(* Logix 5000 project; controller ANG1E_AOI_sample_RSLogix_V31 vendor 1 type 14 code 108 rev 31.11; software revision 31.02; part 5 of 5 *)

ADD_ON_INSTRUCTION AMCI_ANG1E_Reset_Errors   (* revision 1.1, vendor AMCI *)
// Revision note:
// Version 1.1 added the slot_axis number and the input parameters can now be tags or discrete values.
VAR_INPUT
   slot_axis_number : INT; {required}
END_VAR
VAR_IN_OUT
   AMCI_ANG1E_output_data : INT[10]; {required}
END_VAR
VAR
   command_data_block : INT[10];
        [1]   // Command Bits LSW
        [3]   // Lower Target Position
        [5]   // Lower Programmed Speed
        [0]   // Command Bits MSW
        [2]   // Upper Target Position
        [4]   // Upper Programmed Speed
   index : INT;
END_VAR

ROUTINE Logic   (* ladder *)
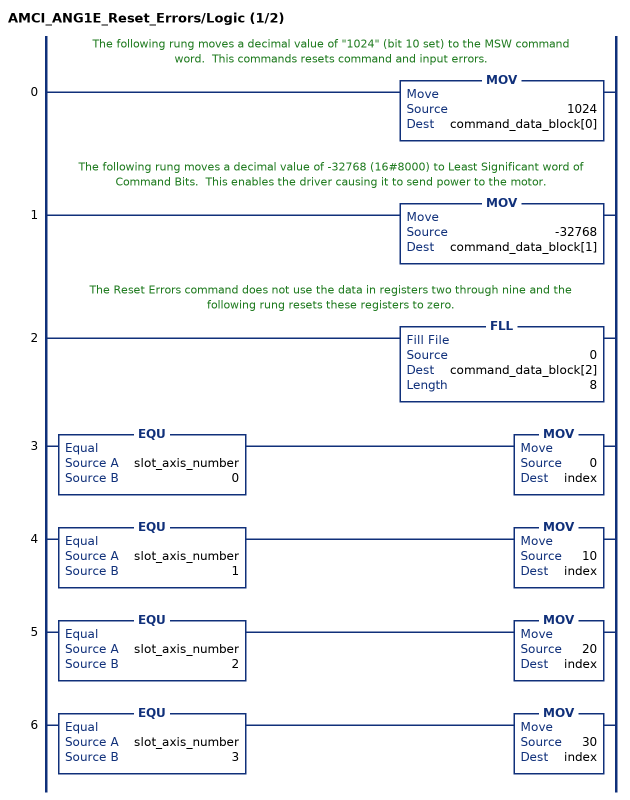
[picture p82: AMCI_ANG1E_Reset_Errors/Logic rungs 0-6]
   // The following rung moves a decimal value of "1024" (bit 10 set) to the MSW command word.  This commands resets command and input errors.
   0: MOV(1024,command_data_block[0]);
   // The following rung moves a decimal value of -32768 (16#8000) to Least Significant word of Command Bits.  This enables the driver causing it to send power to the motor.
   1: MOV(-32768,command_data_block[1]);
   // The Reset Errors command does not use the data in registers two through nine and the following rung resets these registers to zero.
   2: FLL(0,command_data_block[2],8);
   3: EQU(slot_axis_number,0)MOV(0,index);
   4: EQU(slot_axis_number,1)MOV(10,index);
   5: EQU(slot_axis_number,2)MOV(20,index);
   6: EQU(slot_axis_number,3)MOV(30,index);
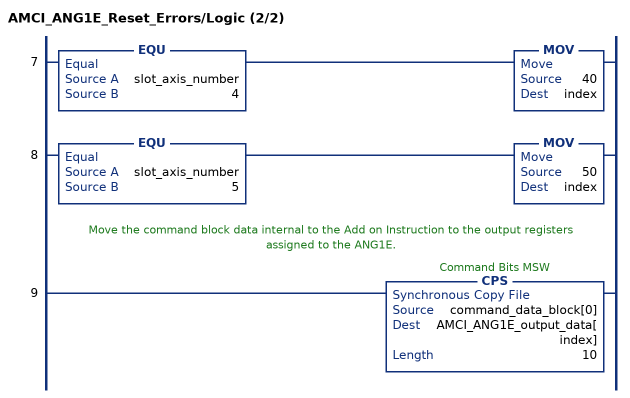
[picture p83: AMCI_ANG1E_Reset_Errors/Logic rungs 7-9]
   7: EQU(slot_axis_number,4)MOV(40,index);
   8: EQU(slot_axis_number,5)MOV(50,index);
   // Move the command block data internal to the Add on Instruction to the output registers assigned to the ANG1E.
   9: CPS(command_data_block[0],AMCI_ANG1E_output_data[index],10);
END_ROUTINE
END_ADD_ON_INSTRUCTION

ADD_ON_INSTRUCTION AMCI_ANG1E_Resume   (* revision 2.0, vendor AMCI *)
// Revision note:
// Version 1.1 added the slot_axis number and the input parameters can now be tags or discrete values.
// 12/4/2023, revision 2.0: Modified AOI so it only writes to output words 0 and 1.
VAR_INPUT
   slot_axis_number : INT; {required}
END_VAR
VAR_IN_OUT
   AMCI_ANG1E_output_data : INT[10]; {required}
END_VAR
VAR
   command_data_block : INT[10];
        [1]   // Command Bits LSW
        [3]   // Lower Target Position
        [5]   // Lower Programmed Speed
        [0]   // Command Bits MSW
        [2]   // Upper Target Position
        [4]   // Upper Programmed Speed
   index : INT;
END_VAR

ROUTINE Logic   (* ladder *)
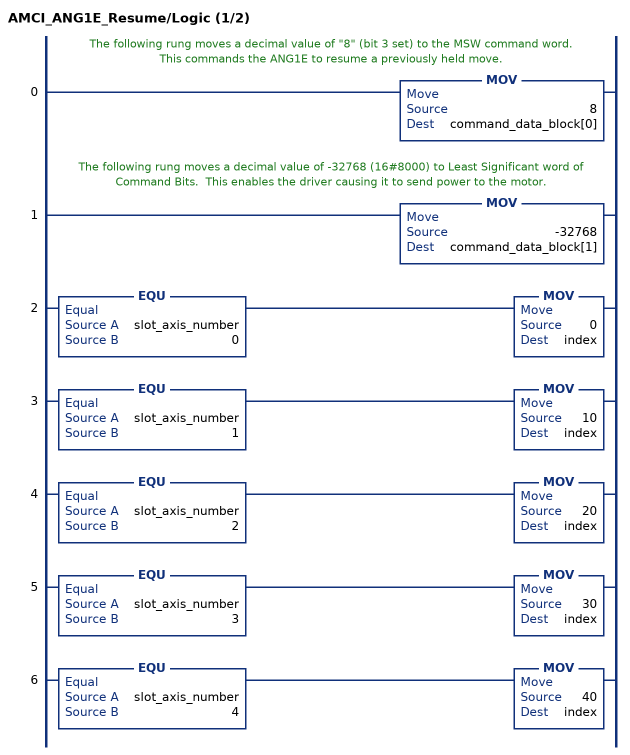
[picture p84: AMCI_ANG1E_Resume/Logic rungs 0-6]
   // The following rung moves a decimal value of "8" (bit 3 set) to the MSW command word.  This commands the ANG1E to resume a previously held move.
   0: MOV(8,command_data_block[0]);
   // The following rung moves a decimal value of -32768 (16#8000) to Least Significant word of Command Bits.  This enables the driver causing it to send power to the motor.
   1: MOV(-32768,command_data_block[1]);
   2: EQU(slot_axis_number,0)MOV(0,index);
   3: EQU(slot_axis_number,1)MOV(10,index);
   4: EQU(slot_axis_number,2)MOV(20,index);
   5: EQU(slot_axis_number,3)MOV(30,index);
   6: EQU(slot_axis_number,4)MOV(40,index);
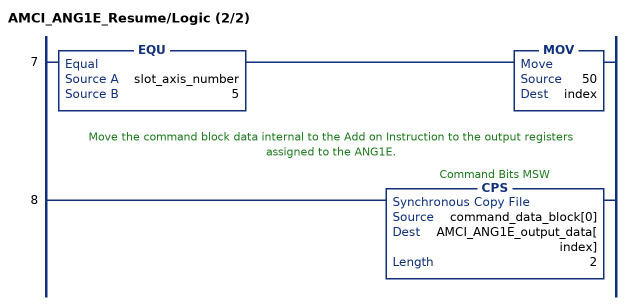
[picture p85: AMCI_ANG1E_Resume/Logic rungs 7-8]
   7: EQU(slot_axis_number,5)MOV(50,index);
   // Move the command block data internal to the Add on Instruction to the output registers assigned to the ANG1E.
   8: CPS(command_data_block[0],AMCI_ANG1E_output_data[index],2);
END_ROUTINE
END_ADD_ON_INSTRUCTION

ADD_ON_INSTRUCTION AMCI_ANG1E_Run_Blend_Move   (* revision 5.0, vendor AMCI, ExecuteEnableInFalse *)
// Revision note:
// Version 5.0 added the (hidden) ability to program the motor current and unlatched the error bit if the rung goes false.
VAR_INPUT
   Axis_Status_bits : INT; {required}
   slot_axis_number : INT; {required}
   Direction_0_for_CW_1_for_CCW : BOOL; {required}
   Type_0_for_standard_1_for_indexed : BOOL;
   motor_current : INT;
END_VAR
VAR_IN_OUT
   AMCI_ANG1E_output_data : INT[10]; {required}
END_VAR
VAR_OUTPUT
   EN : BOOL; {access Read Only, visible}
   ER : BOOL; {access Read Only, visible}
END_VAR
VAR
   command_data_block : INT[10];
        [1]   // Command Bits LSW
        [3]   // Lower Target Position
        [5]   // Lower Programmed Speed
        [0]   // Command Bits MSW
        [2]   // Upper Target Position
        [4]   // Upper Programmed Speed
   index : INT;
END_VAR

ROUTINE EnableInFalse   (* ladder *)
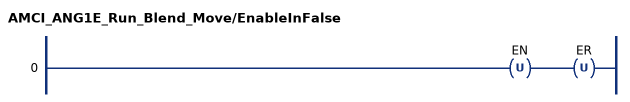
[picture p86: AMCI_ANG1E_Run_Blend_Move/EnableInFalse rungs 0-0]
   0: OTU(EN)OTU(ER);
END_ROUTINE

ROUTINE Logic   (* ladder *)
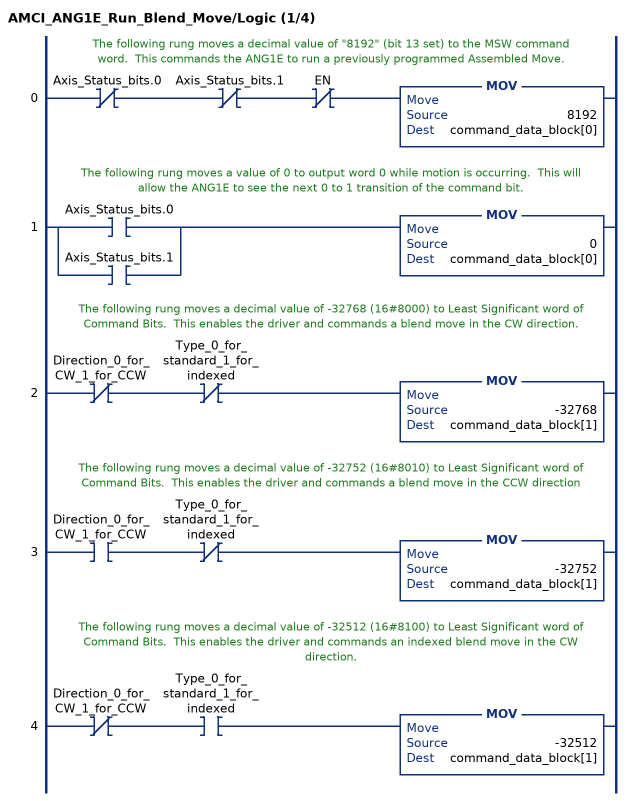
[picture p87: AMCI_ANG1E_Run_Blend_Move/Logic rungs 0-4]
   // The following rung moves a decimal value of "8192" (bit 13 set) to the MSW command word.  This commands the ANG1E to run a previously programmed Assembled Move.
   0: XIO(Axis_Status_bits.0)XIO(Axis_Status_bits.1)XIO(EN)MOV(8192,command_data_block[0]);
   // The following rung moves a value of 0 to output word 0 while motion is occurring.  This will allow the ANG1E to see the next 0 to 1 transition of the command bit.
   1: [XIC(Axis_Status_bits.0) ,XIC(Axis_Status_bits.1) ]MOV(0,command_data_block[0]);
   // The following rung moves a decimal value of -32768 (16#8000) to Least Significant word of Command Bits.  This enables the driver and commands a blend move in the CW direction.
   2: XIO(Direction_0_for_CW_1_for_CCW)XIO(Type_0_for_standard_1_for_indexed)MOV(-32768,command_data_block[1]);
   // The following rung moves a decimal value of -32752 (16#8010) to Least Significant word of Command Bits.  This enables the driver and commands a blend move in the CCW direction
   3: XIC(Direction_0_for_CW_1_for_CCW)XIO(Type_0_for_standard_1_for_indexed)MOV(-32752,command_data_block[1]);
   // The following rung moves a decimal value of -32512 (16#8100) to Least Significant word of Command Bits.  This enables the driver and commands an indexed blend move in the CW direction.
   4: XIO(Direction_0_for_CW_1_for_CCW)XIC(Type_0_for_standard_1_for_indexed)MOV(-32512,command_data_block[1]);
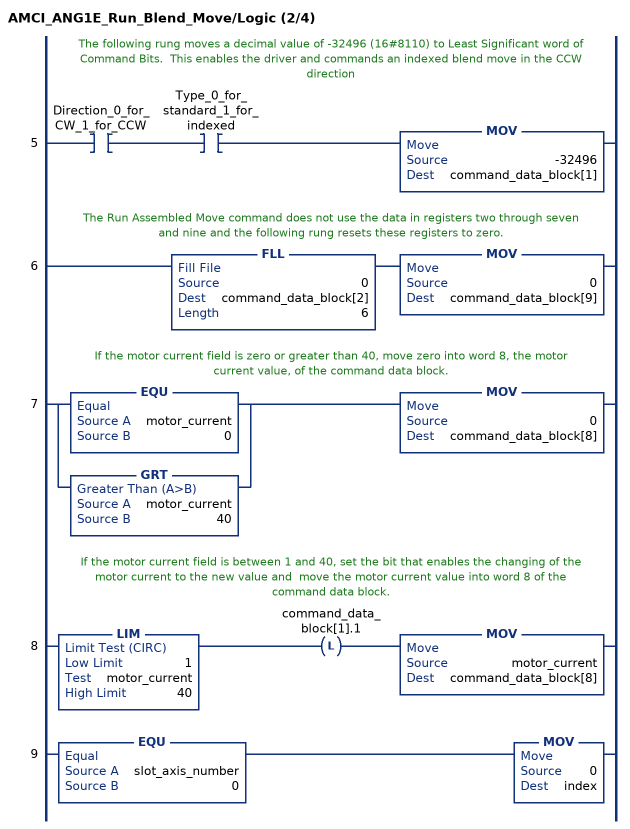
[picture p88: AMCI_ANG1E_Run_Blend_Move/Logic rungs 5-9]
   // The following rung moves a decimal value of -32496 (16#8110) to Least Significant word of Command Bits.  This enables the driver and commands an indexed blend move in the CCW direction
   5: XIC(Direction_0_for_CW_1_for_CCW)XIC(Type_0_for_standard_1_for_indexed)MOV(-32496,command_data_block[1]);
   // The Run Assembled Move command does not use the data in registers two through seven and nine and the following rung resets these registers to zero.
   6: FLL(0,command_data_block[2],6)MOV(0,command_data_block[9]);
   // If the motor current field is zero or greater than 40, move zero into word 8, the motor current value, of the command data block.
   7: [EQU(motor_current,0) ,GRT(motor_current,40) ]MOV(0,command_data_block[8]);
   // If the motor current field is between 1 and 40, set the bit that enables the changing of the motor current to the new value and  move the motor current value into word 8 of the command data block.
   8: LIM(1,motor_current,40)OTL(command_data_block[1].1)MOV(motor_current,command_data_block[8]);
   9: EQU(slot_axis_number,0)MOV(0,index);
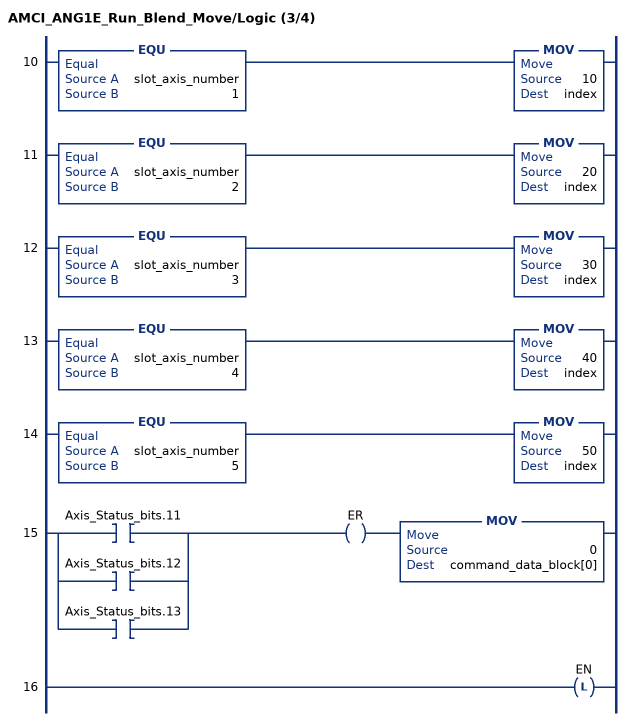
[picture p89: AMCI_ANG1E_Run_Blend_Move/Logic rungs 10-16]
   10: EQU(slot_axis_number,1)MOV(10,index);
   11: EQU(slot_axis_number,2)MOV(20,index);
   12: EQU(slot_axis_number,3)MOV(30,index);
   13: EQU(slot_axis_number,4)MOV(40,index);
   14: EQU(slot_axis_number,5)MOV(50,index);
   15: [XIC(Axis_Status_bits.11) ,XIC(Axis_Status_bits.12) ,XIC(Axis_Status_bits.13) ]OTE(ER)MOV(0,command_data_block[0]);
   16: OTL(EN);
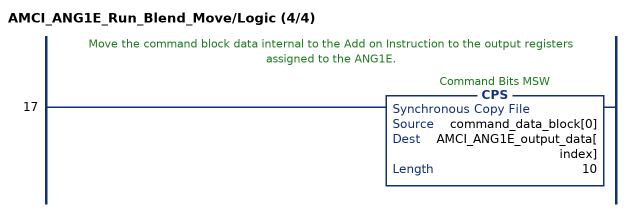
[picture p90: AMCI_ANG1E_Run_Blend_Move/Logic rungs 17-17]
   // Move the command block data internal to the Add on Instruction to the output registers assigned to the ANG1E.
   17: CPS(command_data_block[0],AMCI_ANG1E_output_data[index],10);
END_ROUTINE
END_ADD_ON_INSTRUCTION

ADD_ON_INSTRUCTION AMCI_ANG1E_Run_Dwell_Move   (* revision 5.0, vendor AMCI, ExecuteEnableInFalse *)
// Revision note:
// Version 5.0 added the (hidden) ability to program the motor current and unlatched the error bit if the rung goes false.
VAR_INPUT
   Axis_Status_Bits : INT; {required}
   slot_axis_number : INT; {required}
   Assembed_Move_Dwell_Time : INT; {required}
   Type_0_for_standard_1_for_indexed : BOOL;
   motor_current : INT;
END_VAR
VAR_IN_OUT
   AMCI_ANG1E_output_data : INT[10]; {required}
END_VAR
VAR_OUTPUT
   EN : BOOL; {access Read Only, visible}
   ER : BOOL; {access Read Only, visible}
END_VAR
VAR
   command_data_block : INT[10];
        [1]   // Command Bits LSW
        [3]   // Lower Target Position
        [5]   // Lower Programmed Speed
        [0]   // Command Bits MSW
        [2]   // Upper Target Position
        [4]   // Upper Programmed Speed
   index : INT;
END_VAR

ROUTINE EnableInFalse   (* ladder *)
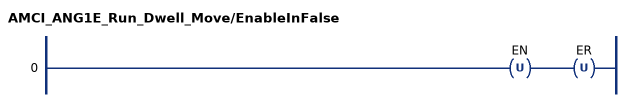
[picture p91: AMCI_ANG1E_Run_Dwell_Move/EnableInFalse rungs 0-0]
   0: OTU(EN)OTU(ER);
END_ROUTINE

ROUTINE Logic   (* ladder *)
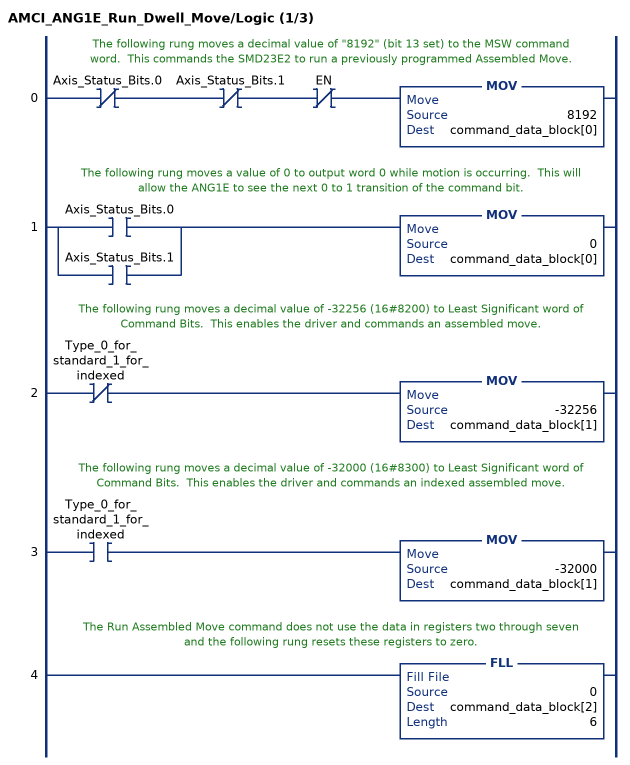
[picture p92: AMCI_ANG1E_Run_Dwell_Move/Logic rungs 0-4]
   // The following rung moves a decimal value of "8192" (bit 13 set) to the MSW command word.  This commands the SMD23E2 to run a previously programmed Assembled Move.
   0: XIO(Axis_Status_Bits.0)XIO(Axis_Status_Bits.1)XIO(EN)MOV(8192,command_data_block[0]);
   // The following rung moves a value of 0 to output word 0 while motion is occurring.  This will allow the ANG1E to see the next 0 to 1 transition of the command bit.
   1: [XIC(Axis_Status_Bits.0) ,XIC(Axis_Status_Bits.1) ]MOV(0,command_data_block[0]);
   // The following rung moves a decimal value of -32256 (16#8200) to Least Significant word of Command Bits.  This enables the driver and commands an assembled move.
   2: XIO(Type_0_for_standard_1_for_indexed)MOV(-32256,command_data_block[1]);
   // The following rung moves a decimal value of -32000 (16#8300) to Least Significant word of Command Bits.  This enables the driver and commands an indexed assembled move.
   3: XIC(Type_0_for_standard_1_for_indexed)MOV(-32000,command_data_block[1]);
   // The Run Assembled Move command does not use the data in registers two through seven and the following rung resets these registers to zero.
   4: FLL(0,command_data_block[2],6);
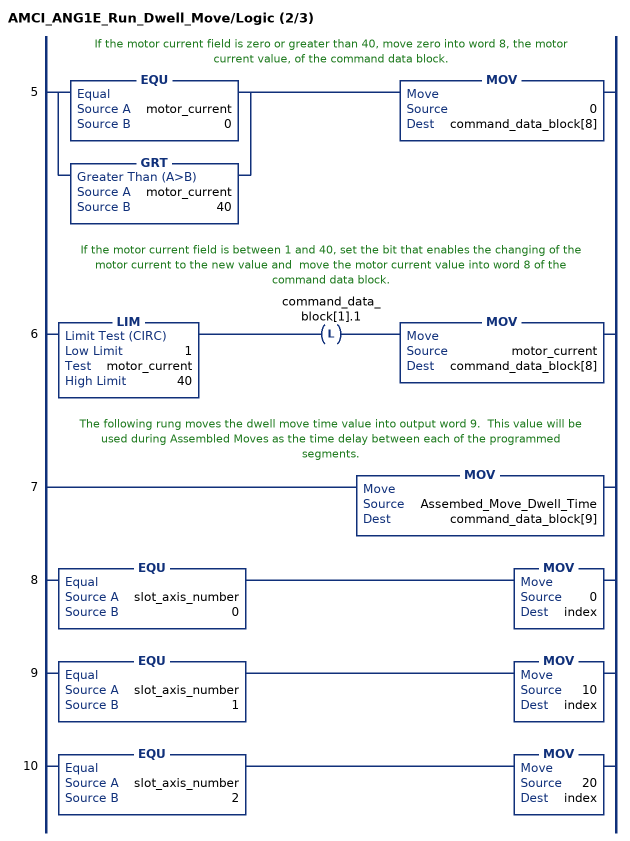
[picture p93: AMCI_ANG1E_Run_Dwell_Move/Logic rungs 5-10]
   // If the motor current field is zero or greater than 40, move zero into word 8, the motor current value, of the command data block.
   5: [EQU(motor_current,0) ,GRT(motor_current,40) ]MOV(0,command_data_block[8]);
   // If the motor current field is between 1 and 40, set the bit that enables the changing of the motor current to the new value and  move the motor current value into word 8 of the command data block.
   6: LIM(1,motor_current,40)OTL(command_data_block[1].1)MOV(motor_current,command_data_block[8]);
   // The following rung moves the dwell move time value into output word 9.  This value will be used during Assembled Moves as the time delay between each of the programmed segments.
   7: MOV(Assembed_Move_Dwell_Time,command_data_block[9]);
   8: EQU(slot_axis_number,0)MOV(0,index);
   9: EQU(slot_axis_number,1)MOV(10,index);
   10: EQU(slot_axis_number,2)MOV(20,index);
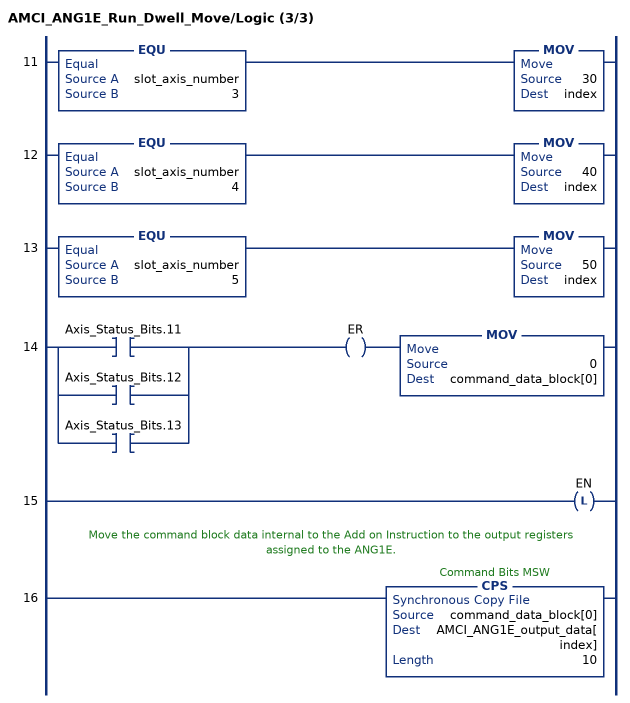
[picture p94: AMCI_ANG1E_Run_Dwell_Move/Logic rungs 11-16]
   11: EQU(slot_axis_number,3)MOV(30,index);
   12: EQU(slot_axis_number,4)MOV(40,index);
   13: EQU(slot_axis_number,5)MOV(50,index);
   14: [XIC(Axis_Status_Bits.11) ,XIC(Axis_Status_Bits.12) ,XIC(Axis_Status_Bits.13) ]OTE(ER)MOV(0,command_data_block[0]);
   15: OTL(EN);
   // Move the command block data internal to the Add on Instruction to the output registers assigned to the ANG1E.
   16: CPS(command_data_block[0],AMCI_ANG1E_output_data[index],10);
END_ROUTINE
END_ADD_ON_INSTRUCTION

VAR_GLOBAL   (* controller tags *)
   ANG1E_Communication_Status : INT;
   ANG1E_Configured : BOOL;   // Set when the AMCI ANG1E has been configured
   ANG1E_Hold : AMCI_ANG1E_Hold;
   ANG1E_manual_configure : BOOL;   // Set to manually send configuration data to the ANG1E
   ANG1E_Resume : AMCI_ANG1E_Resume;
   buffered_ANG1E_data : INT[10];
        [0].13   // AMCI ANG1E configuration error
        [0].14   // AMCI ANG1E OK bit
        [0].15   // AMCI ANG1E mode bit 1=config mode 0=command mode
        [1].15   // AMCI ANG1E set when driver enabled
        [0].9   // set when the SD17060E is ready to receive a blend move segment
        [0].0   // AMCI ANG1E motion occuring CW
        [0].1   // AMCI ANG1E motion occuring CCW
        [0].7   // ANG1E Move Compete bit
        [0].8   // set when SD17060E is in blend move mode
        [1].7   // AMCI ANG1E set when driver fault
        [0].10   // AMCI ANG1E position invalid bit
   CCW_jog_Acceleration : INT := 10;
   CCW_jog_Deceleration : INT := 10;
   CCW_jog_occurring : BOOL;
   CCW_jog_Programmed_Speed : DINT := 2500;
   combined_position : DINT;
   comment : INT;   // used as output instruction on comment rungs
   configuration_ANG1E : ANG1_Driver_Configuration := (Input_1_bit_0 := 1, Input_1_bit_2 := 1, Input_2_bit_4 := 1, Input_2_bit_5 := 1, Mode_bit := 1, Input_1_Active_state := 1, Input_2_Active_state := 1, Input_3_Active_state := 1, Drive_Enable := 1, Lower_Starting_Speed := 100, Motor_Steps_Turn := 400, Idle_current_percentage := 50, Motor_Current_X10 := 20, Current_loop_gain := 1);
   Configure_ANG1E_Manually : INT;
   CW_Home_Acceleration : INT := 10;
   CW_Home_Deceleration : INT := 10;
   CW_Home_Programmed_Speed : DINT := 500;
   CW_jog_Acceleration : INT := 10;
   CW_jog_Deceleration : INT := 10;
   CW_jog_occurring : BOOL;
   CW_jog_Programmed_Speed : DINT := 1250;
   Least_Significant_Word : INT;
   Most_Significant_Word : INT;   // Most Significant Word
   one_shot_1 : BOOL;
   one_shot_2 : BOOL;
   one_shot_3 : BOOL;
   original_value : DINT;
   preset_ANG1E_Target_Position : DINT;
   relative_move_acceleration : INT := 10;
   relative_move_deceleration : INT := 10;
   relative_move_programmed_speed : DINT := 2000;
   relative_move_target_position : DINT := 5000;
   run_ANG1E : INT;   // 1=relative move 2=CW jog 3=CCW jog 4=Reset errors 5=Home CW 6= Preset Position 7=Program Assembled
   starting_speed : DINT := 100;
   upper_resultX1000 : DINT;   // intermediate value
END_VAR

PROGRAM MainProgram   (* main routine MainRoutine *)
VAR
   AOI_ANG1E_Configuration : AMCI_ANG1E_Configure := (Drive_Enable := 1);
   AOI_ANG1E_Program_Assembled_Move : AMCI_ANG1E_Program_Assembled_Move;
   AOI_ANG1E_Run_Blend : AMCI_ANG1E_Run_Blend_Move;
   AOI_ANG1E_run_dwell : AMCI_ANG1E_Run_Dwell_Move;
   AOI_CCW_home : AMCI_ANG1E_Home_CCW;
   AOI_CCW_Jog_Move : AMCI_ANG1E_Jog_CCW;
   AOI_CW_JOG_Move : AMCI_ANG1E_Jog_CW;
   AOI_disable_driver : AMCI_ANG1E_Disable_Driver;
   AOI_Enable_driver : AMCI_ANG1E_Enable_Driver;
   AOI_Enable_ENET_Driver : AMCI_ANG1E_Enable_Driver;
   AOI_Encoder_follower : AMCI_ANG1E_Encoder_Follower;
   AOI_Home_CW : AMCI_ANG1E_Home_CW;
   AOI_immediate_stop : AMCI_ANG1E_Immediate_Stop;
   AOI_preset_encoder : AMCI_ANG1E_Preset_Encoder_Position;
   AOI_Preset_Position : AMCI_ANG1E_Preset_Position;
   AOI_registration_CCW : AMCI_ANG1E_Registration_Move_CCW;
   AOI_registration_CW : AMCI_ANG1E_Registration_Move_CW;
   AOI_Reset_Errors : AMCI_ANG1E_Reset_Errors;
   registration_CCW_occurring : BOOL;
   Registration_CW_occurring : BOOL;
   Relative_Move : AMCI_ANG1E_Relative_Move;
END_VAR

ROUTINE Assembled_Move   (* ladder *)
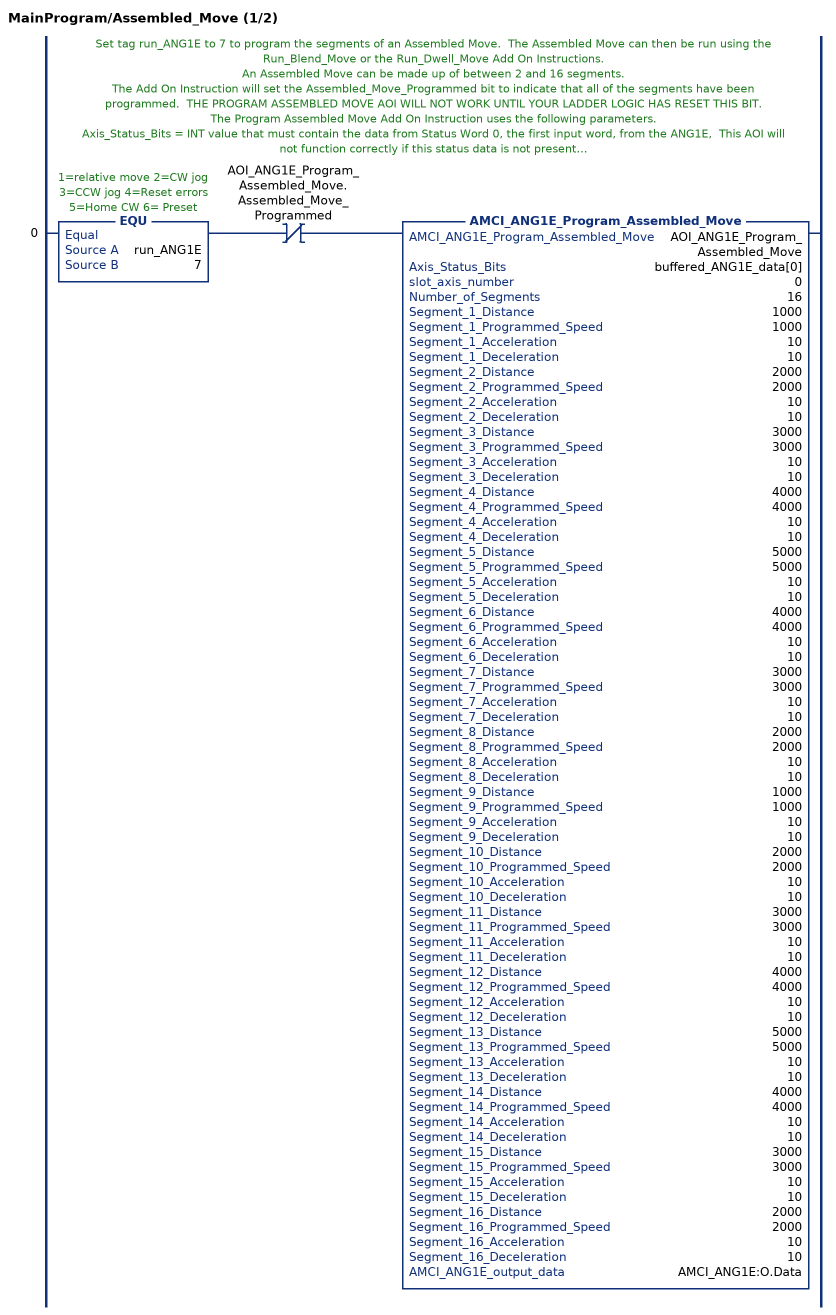
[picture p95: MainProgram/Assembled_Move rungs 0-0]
   // Set tag run_ANG1E to 7 to program the segments of an Assembled Move.  The Assembled Move can then be run using the Run_Blend_Move or the Run_Dwell_Move Add On Instructions.
   // An Assembled Move can be made up of between 2 and 16 segments.
   // The Add On Instruction will set the Assembled_Move_Programmed bit to indicate that all of the segments have been programmed.  THE PROGRAM ASSEMBLED MOVE AOI WILL NOT WORK UNTIL YOUR LADDER LOGIC HAS RESET THIS BIT.
   // The Program Assembled Move Add On Instruction uses the following parameters.
   // Axis_Status_Bits = INT value that must contain the data from Status Word 0, the first input word, from the ANG1E,  This AOI will not function correctly if this status data is not present.
   // NUMBER OF SEGMENTS: An actual value or an INT type register that has a range of 2 to 16 and specifies the number of segments of the Assembled Move.
   // SEGMENT_X_DISTANCE: An actual value or a DINT type register.  The relative distance of each of the Assembled Move Segments.
   // SEGMENT_X_PROGRAMMED_SPEED: An actual value or a DINT type register.  The running speed of each of the programmed segments.
   // SEGMENT_X_ACCELERATION: An actual value or an INT type register that defines how fast the speed of one segment will change to the speed of another segment.
   // SEGMENT_X_Deceleration: An actual value or an INT type register that defines how fast the speed of one segment will change to the speed of another segment.
   // BOOL Assembled_MOVE_Programmed bit indicates when all of the segments have been programmed.
   // The Slot_Axis input parameter has a range of 0 to 5 and defines where in the AnyNet I/O stack the ANG1E is located.  A value of 0 indicates that all of the switches of the ANG1E are off and that it is handling the communication.  A value of 1 indicates that switch 1 is on and switches 2 through 5 are off, up to a value of 5 indicating that switch 5 is on and switches 1 to 4 are off.
   // Register run_ANG1E is only an internal tag used to illustrate how the rung must go from false to true to make the move operation occur, and is set by either manually typing the number into the register or having your ladder logic move a value into the register.  IT IS NOT NECESSASRY TO USE THIS REGISTER OR AN EQUAL INSTRUCTION TO SEND COMMANDS TO THE AMCI ANG1E.  You can replace it with any other condition that makes the rung true, such as a push button on a HMI terminal.
   0: EQU(run_ANG1E,7)XIO(AOI_ANG1E_Program_Assembled_Move.Assembled_Move_Programmed)AMCI_ANG1E_Program_Assembled_Move(AOI_ANG1E_Program_Assembled_Move,buffered_ANG1E_data[0],0,16,1000,1000,10,10,2000,2000,10,10,3000,3000,10,10,4000,4000,10,10,5000,5000,10,10,4000,4000,10,10,3000,3000,10,10,2000,2000,10,10,1000,1000,10,10,2000,2000,10,10,3000,3000,10,10,4000,4000,10,10,5000,5000,10,10,4000,4000,10,10,3000,3000,10,10,2000,2000,10,10,AMCI_ANG1E:O.Data);
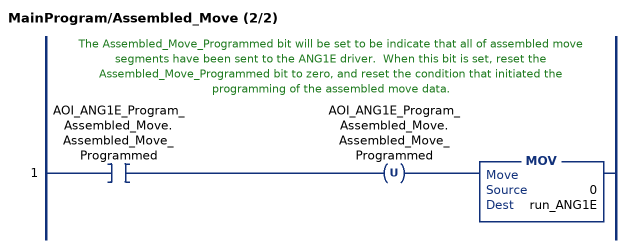
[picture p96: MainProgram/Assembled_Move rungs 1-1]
   // The Assembled_Move_Programmed bit will be set to be indicate that all of assembled move segments have been sent to the ANG1E driver.  When this bit is set, reset the Assembled_Move_Programmed bit to zero, and reset the condition that initiated the programming of the assembled move data.
   1: XIC(AOI_ANG1E_Program_Assembled_Move.Assembled_Move_Programmed)OTU(AOI_ANG1E_Program_Assembled_Move.Assembled_Move_Programmed)MOV(0,run_ANG1E);
END_ROUTINE

ROUTINE combine_separate   (* ladder *)
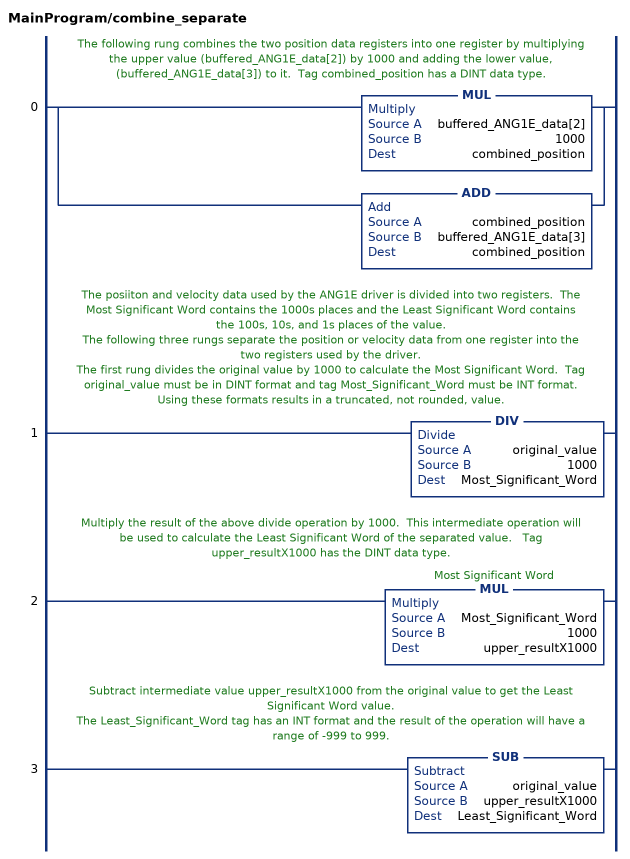
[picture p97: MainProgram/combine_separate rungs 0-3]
   // The following rung combines the two position data registers into one register by multiplying the upper value (buffered_ANG1E_data[2]) by 1000 and adding the lower value, (buffered_ANG1E_data[3]) to it.  Tag combined_position has a DINT data type.
   0: [MUL(buffered_ANG1E_data[2],1000,combined_position) ,ADD(combined_position,buffered_ANG1E_data[3],combined_position) ];
   // The posiiton and velocity data used by the ANG1E driver is divided into two registers.  The Most Significant Word contains the 1000s places and the Least Significant Word contains the 100s, 10s, and 1s places of the value.
   // The following three rungs separate the position or velocity data from one register into the two registers used by the driver.
   // The first rung divides the original value by 1000 to calculate the Most Significant Word.  Tag original_value must be in DINT format and tag Most_Significant_Word must be INT format.  Using these formats results in a truncated, not rounded, value.
   1: DIV(original_value,1000,Most_Significant_Word);
   // Multiply the result of the above divide operation by 1000.  This intermediate operation will be used to calculate the Least Significant Word of the separated value.   Tag upper_resultX1000 has the DINT data type.
   2: MUL(Most_Significant_Word,1000,upper_resultX1000);
   // Subtract intermediate value upper_resultX1000 from the original value to get the Least Significant Word value.
   // The Least_Significant_Word tag has an INT format and the result of the operation will have a range of -999 to 999.
   3: SUB(original_value,upper_resultX1000,Least_Significant_Word);
END_ROUTINE

ROUTINE MainRoutine   (* ladder *)
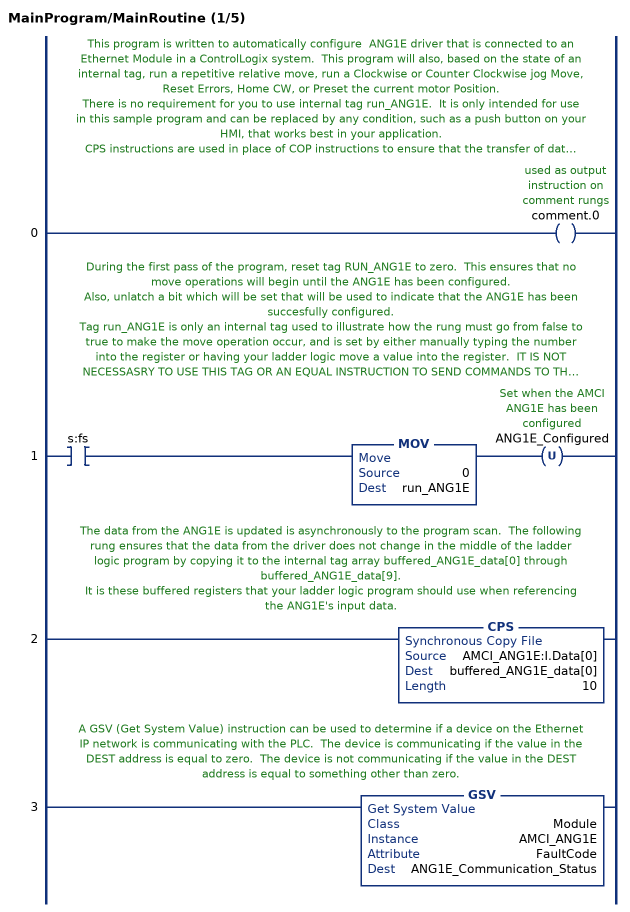
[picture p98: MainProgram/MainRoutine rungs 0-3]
   // This program is written to automatically configure  ANG1E driver that is connected to an Ethernet Module in a ControlLogix system.  This program will also, based on the state of an internal tag, run a repetitive relative move, run a Clockwise or Counter Clockwise jog Move, Reset Errors, Home CW, or Preset the current motor Position.
   // There is no requirement for you to use internal tag run_ANG1E.  It is only intended for use in this sample program and can be replaced by any condition, such as a push button on your HMI, that works best in your application.
   // CPS instructions are used in place of COP instructions to ensure that the transfer of data from the PLC to the ANG1E is not interrupted by RPI I/O update of the driver.
   // This program also used Add On Instructions for most of the ANG1E's functions.  These instructions prompt you for what data is required for the requested move operation, set / reset the appropriate control bits and words, and enable the driver.
   // The ANG1E was added to the Ethernet network using the Generic Module Profile.  The Add On instructions used in this sample program are based on the tags created by the Generic Module profile.
   // Some of the Add On Instructions have some of the less commonly used functions, such as Indexed Moves or Acceleration Jerk, hidden.   The Add On Instructions are not locked or protected and, if desired, these functions can be made visible and enabled.
   // This sample program has asubroutine that explains and shows the use of one of the more complex Add On Instructions, Program Assembled Move.  Ignore or delete this subroutine if you are not using this function.
   // Subroutine combine_separate is not used by the program.  It is included here to demonstrate one method of combining the two position data words from the ANG1E into one DINT tag, and also how to separate one DINT tag value into the two word format used by the ANG1E.
   0: OTE(comment.0);
   // During the first pass of the program, reset tag RUN_ANG1E to zero.  This ensures that no move operations will begin until the ANG1E has been configured.
   // Also, unlatch a bit which will be set that will be used to indicate that the ANG1E has been succesfully configured.
   // Tag run_ANG1E is only an internal tag used to illustrate how the rung must go from false to true to make the move operation occur, and is set by either manually typing the number into the register or having your ladder logic move a value into the register.  IT IS NOT NECESSASRY TO USE THIS TAG OR AN EQUAL INSTRUCTION TO SEND COMMANDS TO THE AMCI ANG1E.  You can replace it with any other condition that makes the rung true, such as a push button on a Panelview terminal.
   1: XIC(s:fs)MOV(0,run_ANG1E)OTU(ANG1E_Configured);
   // The data from the ANG1E is updated is asynchronously to the program scan.  The following rung ensures that the data from the driver does not change in the middle of the ladder logic program by copying it to the internal tag array buffered_ANG1E_data[0] through buffered_ANG1E_data[9].
   // It is these buffered registers that your ladder logic program should use when referencing the ANG1E's input data.
   2: CPS(AMCI_ANG1E:I.Data[0],buffered_ANG1E_data[0],10);
   // A GSV (Get System Value) instruction can be used to determine if a device on the Ethernet IP network is communicating with the PLC.  The device is communicating if the value in the DEST address is equal to zero.  The device is not communicating if the value in the DEST address is equal to something other than zero.
   3: GSV(Module,AMCI_ANG1E,FaultCode,ANG1E_Communication_Status);
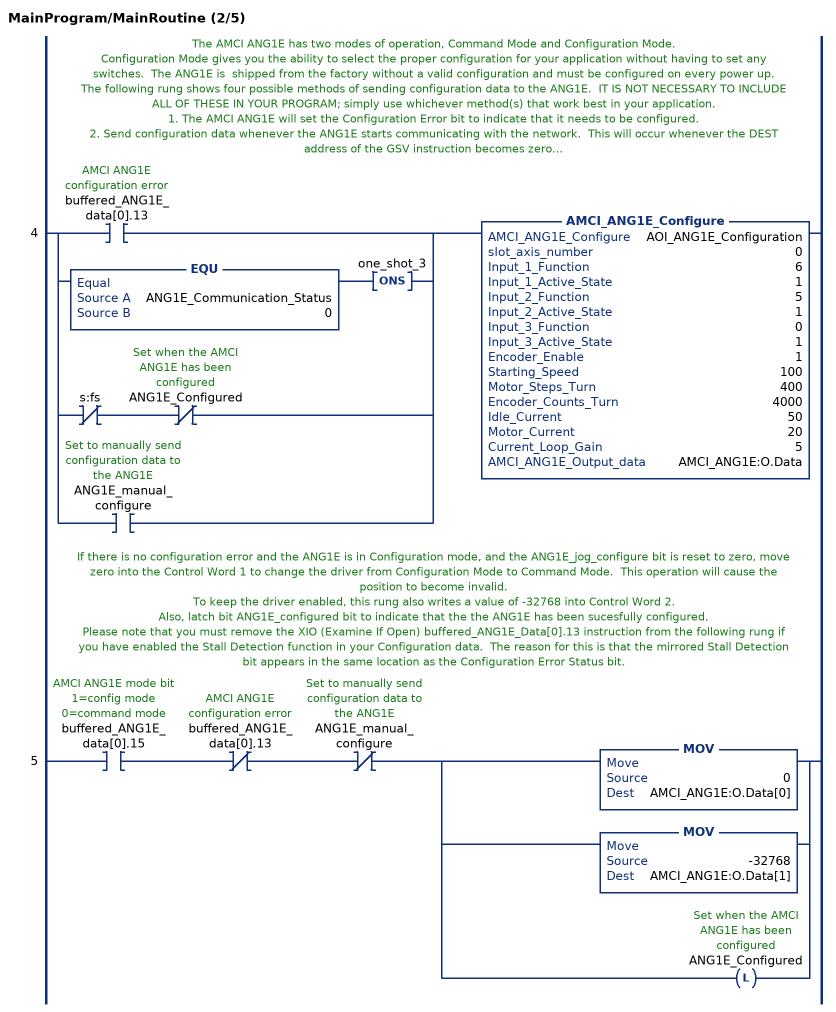
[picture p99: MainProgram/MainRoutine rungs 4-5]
   // The AMCI ANG1E has two modes of operation, Command Mode and Configuration Mode.
   // Configuration Mode gives you the ability to select the proper configuration for your application without having to set any switches.  The ANG1E is  shipped from the factory without a valid configuration and must be configured on every power up.
   // The following rung shows four possible methods of sending configuration data to the ANG1E.  IT IS NOT NECESSARY TO INCLUDE ALL OF THESE IN YOUR PROGRAM; simply use whichever method(s) that work best in your application.
   // 1. The AMCI ANG1E will set the Configuration Error bit to indicate that it needs to be configured.
   // 2. Send configuration data whenever the ANG1E starts communicating with the network.  This will occur whenever the DEST address of the GSV instruction becomes zero.
   // 3. Send configuration data at every power up, or when the PLC is switched from Program to Run, based on the state of both the first pass bit and an internal status bit.
   // 4. Send the configuration data when an internal bit is set either manually or by the ladder logic program.  This bit, ANG1E_jog_configure in this example, must transition from ON to OFF before any move operations will be allowed.
   // The Slot_Axis input parameter has a range of 0 to 5 and defines where in the AnyNet I/O stack the ANG1E is located.  A value of 0 indicates that all of the switches of the ANG1E are off and that it is handling the communication.  A value of 1 indicates that switch 1 is on and switches 2 through 5 are off, up to a value of 5 indicating that switch 5 is on and switches 1 to 4 are off.
   // Each of the Input Function parameters has a range of 0 to 6, where each value represents a different input function.
   // 0 = General purpose
   // 1=CW Limit
   // 2=CCW Limit
   // 3=Start Indexed Move / Capture Encoder Value
   // 4=Stop jog or Registration Move and Capture Encoder Value
   // 5=Emergency Stop
   // 6=Home
   // The Input Active State = “1” for Active High or “0” for Active Low
   // The configure Add On Instruction also has less used hidden parameters that can be enabled if you want to use them.
   4: [XIC(buffered_ANG1E_data[0].13) ,EQU(ANG1E_Communication_Status,0) ONS(one_shot_3) ,XIO(s:fs) XIO(ANG1E_Configured) ,XIC(ANG1E_manual_configure) ]AMCI_ANG1E_Configure(AOI_ANG1E_Configuration,0,6,1,5,1,0,1,1,100,400,4000,50,20,5,AMCI_ANG1E:O.Data);
   // If there is no configuration error and the ANG1E is in Configuration mode, and the ANG1E_jog_configure bit is reset to zero, move zero into the Control Word 1 to change the driver from Configuration Mode to Command Mode.  This operation will cause the position to become invalid.
   // To keep the driver enabled, this rung also writes a value of -32768 into Control Word 2.
   // Also, latch bit ANG1E_configured bit to indicate that the the ANG1E has been sucesfully configured.
   // Please note that you must remove the XIO (Examine If Open) buffered_ANG1E_Data[0].13 instruction from the following rung if you have enabled the Stall Detection function in your Configuration data.  The reason for this is that the mirrored Stall Detection bit appears in the same location as the Configuration Error Status bit.
   5: XIC(buffered_ANG1E_data[0].15)XIO(buffered_ANG1E_data[0].13)XIO(ANG1E_manual_configure)[MOV(0,AMCI_ANG1E:O.Data[0]) ,MOV(-32768,AMCI_ANG1E:O.Data[1]) ,OTL(ANG1E_Configured) ];
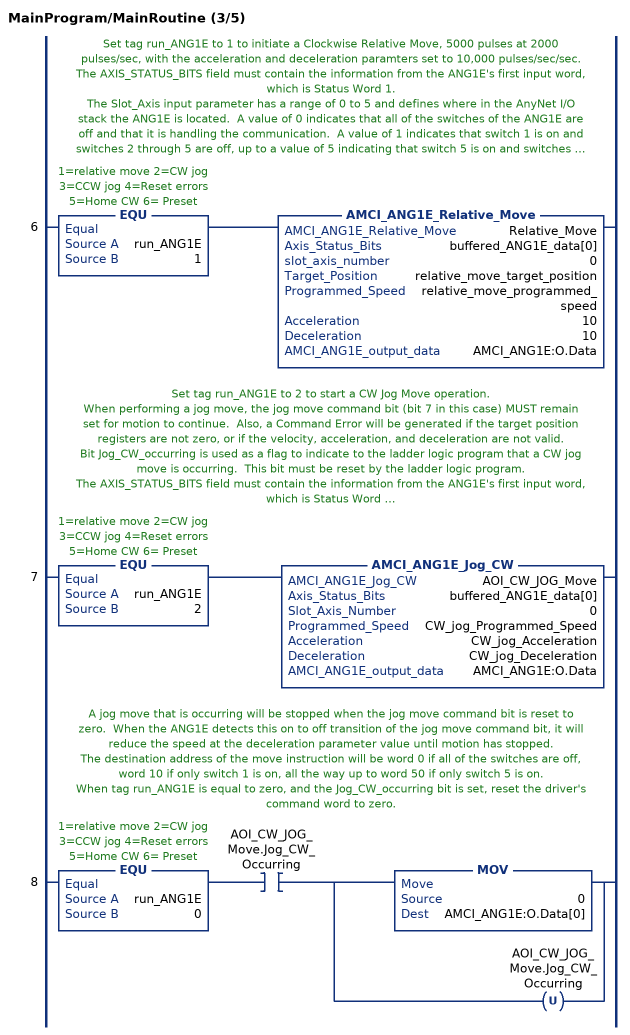
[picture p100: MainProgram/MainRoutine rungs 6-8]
   // Set tag run_ANG1E to 1 to initiate a Clockwise Relative Move, 5000 pulses at 2000 pulses/sec, with the acceleration and deceleration paramters set to 10,000 pulses/sec/sec.
   // The AXIS_STATUS_BITS field must contain the information from the ANG1E's first input word, which is Status Word 1.
   // The Slot_Axis input parameter has a range of 0 to 5 and defines where in the AnyNet I/O stack the ANG1E is located.  A value of 0 indicates that all of the switches of the ANG1E are off and that it is handling the communication.  A value of 1 indicates that switch 1 is on and switches 2 through 5 are off, up to a value of 5 indicating that switch 5 is on and switches 1 to 4 are off.
   // The rung must go from false to true before another relative move can occur.
   // Tag run_ANG1E is only an internal tag used to illustrate how the rung must go from false to true to make the move operation occur, and is set by either manually typing the number into the register or having your ladder logic move a value into the register.  IT IS NOT NECESSASRY TO USE THIS TAG OR AN EQUAL INSTRUCTION TO SEND COMMANDS TO THE AMCI ANG1E.  You can replace it with any other condition that makes the rung true, such as a push button on a Panelview terminal.
   6: EQU(run_ANG1E,1)AMCI_ANG1E_Relative_Move(Relative_Move,buffered_ANG1E_data[0],0,relative_move_target_position,relative_move_programmed_speed,10,10,AMCI_ANG1E:O.Data);
   // Set tag run_ANG1E to 2 to start a CW Jog Move operation.
   // When performing a jog move, the jog move command bit (bit 7 in this case) MUST remain set for motion to continue.  Also, a Command Error will be generated if the target position registers are not zero, or if the velocity, acceleration, and deceleration are not valid.
   // Bit Jog_CW_occurring is used as a flag to indicate to the ladder logic program that a CW jog move is occurring.  This bit must be reset by the ladder logic program.
   // The AXIS_STATUS_BITS field must contain the information from the ANG1E's first input word, which is Status Word 1
   // The Slot_Axis input parameter has a range of 0 to 5 and defines where in the AnyNet I/O stack the ANG1E is located.  A value of 0 indicates that all of the switches of the ANG1E are off and that it is handling the communication.  A value of 1 indicates that switch 1 is on and switches 2 through 5 are off, up to a value of 5 indicating that switch 5 is on and switches 1 to 4 are off.
   // Tag run_ANG1E is only an internal tag used to illustrate how the rung must go from false to true to make the move operation occur, and is set by either manually typing the number into the register or having your ladder logic move a value into the register.  IT IS NOT NECESSASRY TO USE THIS TAG OR AN EQUAL INSTRUCTION TO SEND COMMANDS TO THE AMCI ANG1E.  You can replace it with any other condition that makes the rung true, such as a push button on a Panelview terminal.
   7: EQU(run_ANG1E,2)AMCI_ANG1E_Jog_CW(AOI_CW_JOG_Move,buffered_ANG1E_data[0],0,CW_jog_Programmed_Speed,CW_jog_Acceleration,CW_jog_Deceleration,AMCI_ANG1E:O.Data);
   // A jog move that is occurring will be stopped when the jog move command bit is reset to zero.  When the ANG1E detects this on to off transition of the jog move command bit, it will reduce the speed at the deceleration parameter value until motion has stopped.
   // The destination address of the move instruction will be word 0 if all of the switches are off, word 10 if only switch 1 is on, all the way up to word 50 if only switch 5 is on.
   // When tag run_ANG1E is equal to zero, and the Jog_CW_occurring bit is set, reset the driver's command word to zero.
   8: EQU(run_ANG1E,0)XIC(AOI_CW_JOG_Move.Jog_CW_Occurring)[MOV(0,AMCI_ANG1E:O.Data[0]) ,OTU(AOI_CW_JOG_Move.Jog_CW_Occurring) ];
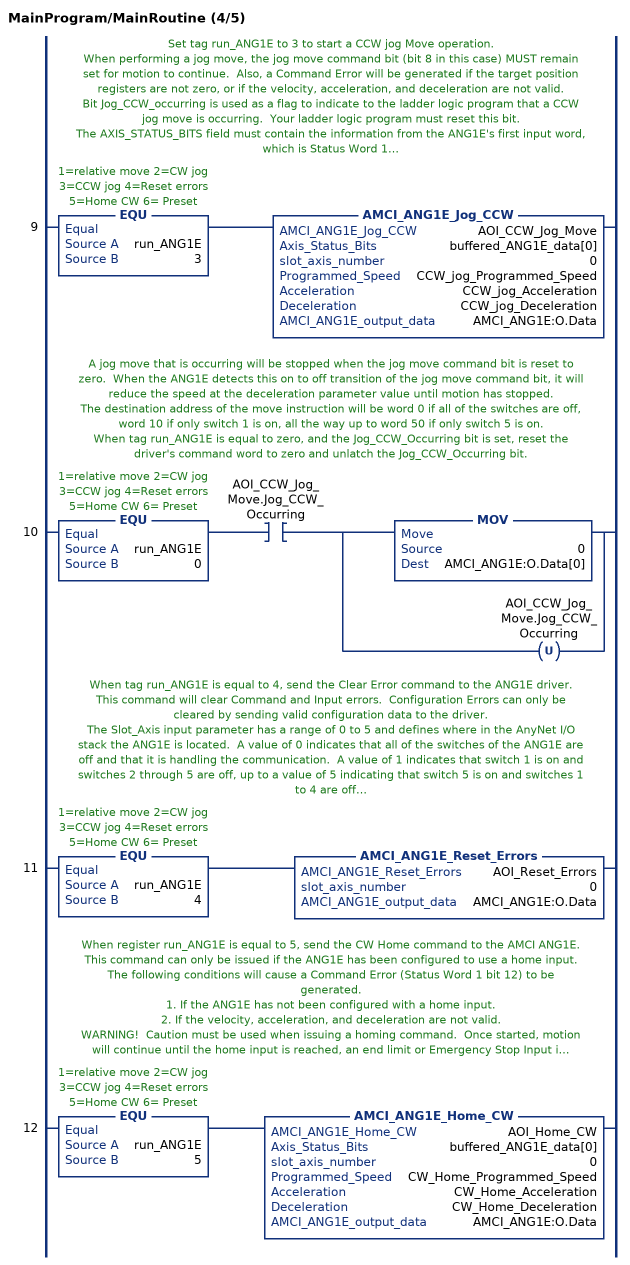
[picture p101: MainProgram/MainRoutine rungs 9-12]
   // Set tag run_ANG1E to 3 to start a CCW jog Move operation.
   // When performing a jog move, the jog move command bit (bit 8 in this case) MUST remain set for motion to continue.  Also, a Command Error will be generated if the target position registers are not zero, or if the velocity, acceleration, and deceleration are not valid.
   // Bit Jog_CCW_occurring is used as a flag to indicate to the ladder logic program that a CCW jog move is occurring.  Your ladder logic program must reset this bit.
   // The AXIS_STATUS_BITS field must contain the information from the ANG1E's first input word, which is Status Word 1.
   // The Slot_Axis input parameter has a range of 0 to 5 and defines where in the AnyNet I/O stack the ANG1E is located.  A value of 0 indicates that all of the switches of the ANG1E are off and that it is handling the communication.  A value of 1 indicates that switch 1 is on and switches 2 through 5 are off, up to a value of 5 indicating that switch 5 is on and switches 1 to 4 are off.
   // Tag run_ANG1E is only an internal tag used to illustrate how the rung must go from false to true to make the move operation occur, and is set by either manually typing the number into the register or having your ladder logic move a value into the register.  IT IS NOT NECESSASRY TO USE THIS TAG OR AN EQUAL INSTRUCTION TO SEND COMMANDS TO THE AMCI ANG1E.  You can replace it with any other condition that makes the rung true, such as a push button on a Panelview terminal.
   9: EQU(run_ANG1E,3)AMCI_ANG1E_Jog_CCW(AOI_CCW_Jog_Move,buffered_ANG1E_data[0],0,CCW_jog_Programmed_Speed,CCW_jog_Acceleration,CCW_jog_Deceleration,AMCI_ANG1E:O.Data);
   // A jog move that is occurring will be stopped when the jog move command bit is reset to zero.  When the ANG1E detects this on to off transition of the jog move command bit, it will reduce the speed at the deceleration parameter value until motion has stopped.
   // The destination address of the move instruction will be word 0 if all of the switches are off, word 10 if only switch 1 is on, all the way up to word 50 if only switch 5 is on.
   // When tag run_ANG1E is equal to zero, and the Jog_CCW_Occurring bit is set, reset the driver's command word to zero and unlatch the Jog_CCW_Occurring bit.
   10: EQU(run_ANG1E,0)XIC(AOI_CCW_Jog_Move.Jog_CCW_Occurring)[MOV(0,AMCI_ANG1E:O.Data[0]) ,OTU(AOI_CCW_Jog_Move.Jog_CCW_Occurring) ];
   // When tag run_ANG1E is equal to 4, send the Clear Error command to the ANG1E driver.  This command will clear Command and Input errors.  Configuration Errors can only be cleared by sending valid configuration data to the driver.
   // The Slot_Axis input parameter has a range of 0 to 5 and defines where in the AnyNet I/O stack the ANG1E is located.  A value of 0 indicates that all of the switches of the ANG1E are off and that it is handling the communication.  A value of 1 indicates that switch 1 is on and switches 2 through 5 are off, up to a value of 5 indicating that switch 5 is on and switches 1 to 4 are off.
   // Tag run_ANG1E is only an internal tag used to illustrate how the rung must go from false to true to make the move operation occur, and is set by either manually typing the number into the register or having your ladder logic move a value into the register.  IT IS NOT NECESSASRY TO USE THIS TAG OR AN EQUAL INSTRUCTION TO SEND COMMANDS TO THE AMCI ANG1E.  You can replace it with any other condition that makes the rung true, such as a push button on a Panelview terminal.
   11: EQU(run_ANG1E,4)AMCI_ANG1E_Reset_Errors(AOI_Reset_Errors,0,AMCI_ANG1E:O.Data);
   // When register run_ANG1E is equal to 5, send the CW Home command to the AMCI ANG1E.  This command can only be issued if the ANG1E has been configured to use a home input.  The following conditions will cause a Command Error (Status Word 1 bit 12) to be generated.
   // 1. If the ANG1E has not been configured with a home input.
   // 2. If the velocity, acceleration, and deceleration are not valid.
   // WARNING!  Caution must be used when issuing a homing command.  Once started, motion will continue until the home input is reached, an end limit or Emergency Stop Input in reached, or the Immediate Stop Command is issued.  Resetting the command word to zero WILL NOT STOP a home operation.
   // The AXIS_STATUS_BITS field must contain the information from the ANG1E's first input word, which is Status Word 1.
   // The Slot_Axis input parameter has a range of 0 to 5 and defines where in the AnyNet I/O stack the ANG1E is located.  A value of 0 indicates that all of the switches of the ANG1E are off and that it is handling the communication.  A value of 1 indicates that switch 1 is on and switches 2 through 5 are off, up to a value of 5 indicating that switch 5 is on and switches 1 to 4 are off.
   // Register run_ANG1E is only an internal tag used to illustrate how the rung must go from false to true to make the move operation occur, and is set by either manually typing the number into the register or having your ladder logic move a value into the register.  IT IS NOT NECESSASRY TO USE THIS REGISTER OR AN EQUAL INSTRUCTION TO SEND COMMANDS TO THE AMCI ANG1E.  You can replace it with any other condition that makes the rung true, such as a push button on a Panelview terminal.
   12: EQU(run_ANG1E,5)AMCI_ANG1E_Home_CW(AOI_Home_CW,buffered_ANG1E_data[0],0,CW_Home_Programmed_Speed,CW_Home_Acceleration,CW_Home_Deceleration,AMCI_ANG1E:O.Data);
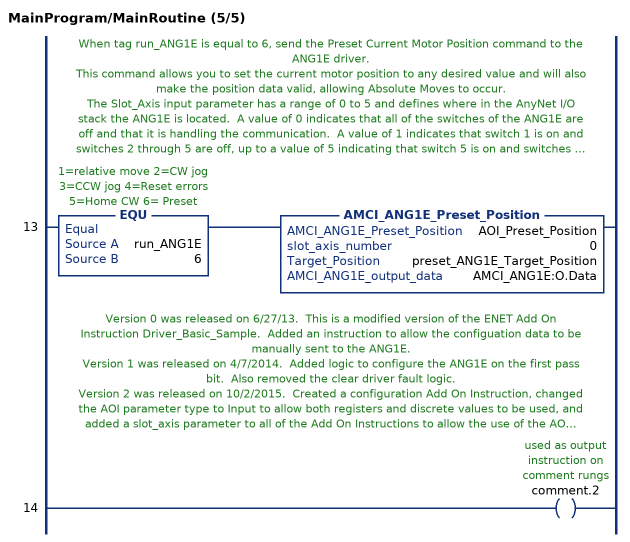
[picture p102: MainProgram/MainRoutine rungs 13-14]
   // When tag run_ANG1E is equal to 6, send the Preset Current Motor Position command to the ANG1E driver.
   // This command allows you to set the current motor position to any desired value and will also make the position data valid, allowing Absolute Moves to occur.
   // The Slot_Axis input parameter has a range of 0 to 5 and defines where in the AnyNet I/O stack the ANG1E is located.  A value of 0 indicates that all of the switches of the ANG1E are off and that it is handling the communication.  A value of 1 indicates that switch 1 is on and switches 2 through 5 are off, up to a value of 5 indicating that switch 5 is on and switches 1 to 4 are off.
   // Register run_ANG1E is only an internal tag used to illustrate how the rung must go from false to true to make the move operation occur, and is set by either manually typing the number into the register or having your ladder logic move a value into the register.  IT IS NOT NECESSASRY TO USE THIS REGISTER OR AN EQUAL INSTRUCTION TO SEND COMMANDS TO THE AMCI ANG1E.  You can replace it with any other condition that makes the rung true, such as a push button on a Panelview terminal.
   13: EQU(run_ANG1E,6)AMCI_ANG1E_Preset_Position(AOI_Preset_Position,0,preset_ANG1E_Target_Position,AMCI_ANG1E:O.Data);
   // Version 0 was released on 6/27/13.  This is a modified version of the ENET Add On Instruction Driver_Basic_Sample.  Added an instruction to allow the configuation data to be manually sent to the ANG1E.
   // Version 1 was released on 4/7/2014.  Added logic to configure the ANG1E on the first pass bit.  Also removed the clear driver fault logic.
   // Version 2 was released on 10/2/2015.  Created a configuration Add On Instruction, changed the AOI parameter type to Input to allow both registers and discrete values to be used, and added a slot_axis parameter to all of the Add On Instructions to allow the use of the AOI with any location in the stack.
   // Version 3 was relesed on 8/24/2016.  Moved the Preset Motor Position command so that it no longer occurs automatically.  Also modified the Add On Instructions so that they contain (hidden) indexed moves and acceleration jerk parameters, and created new AOIs for programming and running assembled moves, and encoder follower moves.
   // Version 4 was released on 6/28/2017 and modified the absolute, relative, home CW, home CCW, run blend, and run dwell moves Add On Instrucitions so that they would automatically reset the command word to zero when motion is occurring.  Also added EN and ER bits to these AOIs and to the jog, egistration, and follower move AOIs.  The logic that caused the relative move to automatically repeat was also removed.
   // Version 5 was released in 6/2019.  Changed to a L71 PLC and an EN2T module.   Modified the Absolute, Relative, Jog, Home, Registration, and run blend / dwell  AOIs so that the Error bit will be unlatched if the rung goes false.    Also modified the Absolute, Relative, Jog, Home, and run blend / dwell AOIs with a hidden parameter allowing the programming of the motor current.
   // Version 6 was released on 12/4/2023.  Modified the Absolute and Relative Move AOIs so that they will issue the Reset Error command if the Move Complete bit is set.  This will allow short moves to occur.  Also modified the Hold and Resume commands so that they only write to output words 0 and 1.  The previous version was resetting words 2 to 9 and the resume command will not work if the position, velocity, acceleration, and deceleration parameters are not present.
   14: OTE(comment.2);
END_ROUTINE
END_PROGRAM
